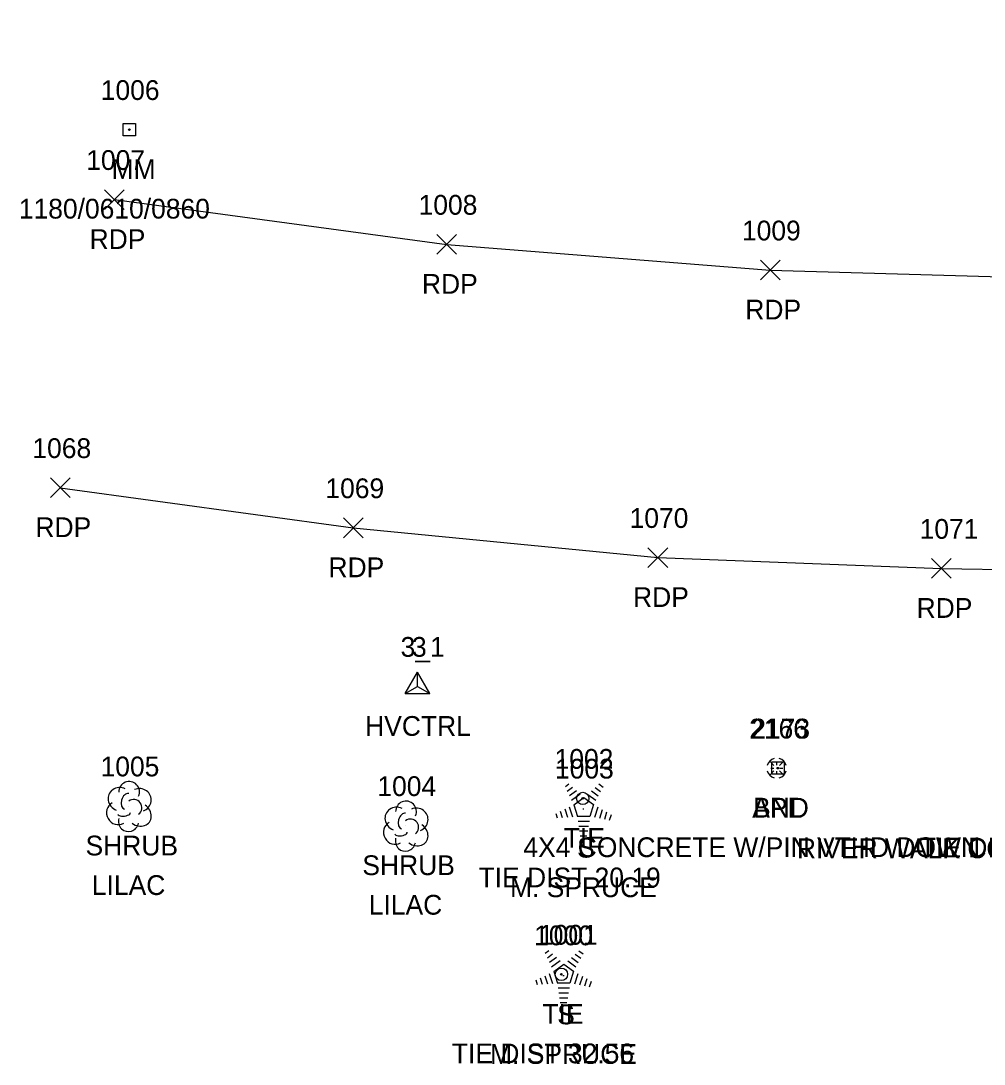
# Model space of a CAD drawing. Extents: x 1600395 to 1603269, y 874955 to 877143.
# Drawn here: x 1601404.6 to 1601502, y 875144.4 to 875250 of the extents above; entities that cross this region are included whole.
import ezdxf

# ---------------------------------------------------------------- set-up
doc = ezdxf.new("R2010")
doc.units = 0
for name, color, linetype in [('C_A', 7, 'Continuous'), ('C_C', 7, 'Continuous'), ('C_I', 7, 'Continuous'), ('CBP', 7, 'Continuous'), ('CPSM', 7, 'Continuous'), ('L_A', 7, 'Continuous'), ('L_C', 7, 'Continuous'), ('L_I', 7, 'Continuous'), ('LSH', 7, 'Continuous'), ('LTC', 7, 'Continuous'), ('M_A', 7, 'Continuous'), ('M_C', 7, 'Continuous'), ('M_I', 7, 'Continuous'), ('MHBP', 7, 'Continuous'), ('MMP', 7, 'Continuous'), ('P_A', 7, 'Continuous'), ('P_I', 7, 'Continuous'), ('P_TIC', 7, 'Continuous'), ('PET', 7, 'Continuous'), ('S_A', 7, 'Continuous'), ('S_C', 7, 'Continuous'), ('S_I', 7, 'Continuous'), ('SRM', 7, 'Continuous')]:
    doc.layers.add(name, color=color, linetype=linetype)

msp = doc.modelspace()

# ---------------------------------------------------------------- linework, layer by layer
at = {"layer": 'CBP'}
for centre, radius in [((1601461.42, 875171.28), 0.625), ((1601461.42, 875171.28), 0.0833), ((1601459.26, 875153.48), 0.625), ((1601459.26, 875153.48), 0.0833)]:
    msp.add_circle(centre, radius, dxfattribs=at)
at = {"layer": 'CPSM'}
for p, q in [((1601443.46, 875181.89), (1601444.71, 875184.06)), ((1601443.46, 875181.89), (1601444.71, 875184.06)), ((1601445.96, 875181.89), (1601444.71, 875184.06)), ((1601444.71, 875182.61), (1601444.71, 875184.06)), ((1601445.96, 875181.89), (1601444.71, 875184.06)), ((1601444.71, 875182.61), (1601444.71, 875184.06)), ((1601443.46, 875181.89), (1601444.71, 875182.61)), ((1601443.46, 875181.89), (1601444.71, 875182.61)), ((1601444.71, 875182.61), (1601444.71, 875182.61)), ((1601444.71, 875182.61), (1601445.96, 875181.89)), ((1601444.71, 875182.61), (1601444.71, 875182.61)), ((1601444.71, 875182.61), (1601445.96, 875181.89)), ((1601443.46, 875181.89), (1601445.96, 875181.89)), ((1601443.46, 875181.89), (1601445.96, 875181.89))]:
    msp.add_line(p, q, dxfattribs=at)
at = {"layer": 'LSH'}
for p, q in [((1601415.48, 875170.51), (1601415.48, 875170.51)), ((1601415.48, 875170.51), (1601415.48, 875170.51)), ((1601443.49, 875168.52), (1601443.49, 875168.52)), ((1601443.49, 875168.52), (1601443.49, 875168.52))]:
    msp.add_line(p, q, dxfattribs=at)
for centre in [(1601415.52, 875171.94), (1601443.54, 875169.96)]:
    msp.add_arc(centre, 1.05, 335.5272, 180.9563, dxfattribs=at)
for centre, major_axis, ratio, start_param, end_param in [((1601414.68, 875171.18), (1.21, -0.51), 0.895232, 1.570796, 4.712389), ((1601415.27, 875170.97), (-0.208, -0.792), 0.645439, 3.141593, 6.283185), ((1601416.52, 875171.09), (-1.14, -0.48), 0.949671, 1.570796, 4.712389), ((1601414.39, 875169.8), (0.58, -1.04), 0.959034, 3.141593, 6.283185), ((1601415.98, 875170.34), (-0.5, 0.667), 0.989748, 3.141593, 6.283185), ((1601415.02, 875169.76), (-0.625, -0.083), 0.423636, 0, 3.141593), ((1601416.48, 875169.68), (-1.09, 0.79), 0.841452, 1.570796, 4.712389), ((1601442.7, 875169.19), (1.21, -0.51), 0.895232, 1.570796, 4.712389), ((1601443.29, 875168.98), (-0.208, -0.792), 0.645439, 3.141593, 6.283185), ((1601444.54, 875169.11), (-1.14, -0.48), 0.949671, 1.570796, 4.712389), ((1601415.48, 875169.01), (0.26, 1.06), 0.942809, 1.570796, 4.712389), ((1601442.41, 875167.81), (0.58, -1.04), 0.959034, 3.141593, 6.283185), ((1601443.99, 875168.36), (-0.5, 0.667), 0.989748, 3.141593, 6.283185), ((1601444.49, 875167.69), (-1.09, 0.79), 0.841452, 1.570796, 4.712389), ((1601443.04, 875167.77), (-0.625, -0.083), 0.423636, 0, 3.141593), ((1601443.49, 875167.02), (0.26, 1.06), 0.942809, 1.570796, 4.712389)]:
    msp.add_ellipse(centre, major_axis=major_axis, ratio=ratio, start_param=start_param, end_param=end_param, dxfattribs=at)
at = {"layer": 'LTC'}
for p, q in [((1601459.66, 875172.5), (1601460.01, 875172.75)), ((1601459.86, 875172.03), (1601460.39, 875172.41)), ((1601460.07, 875171.56), (1601460.78, 875172.08)), ((1601462.31, 875172.04), (1601462.99, 875171.55)), ((1601462.68, 875172.39), (1601463.23, 875171.99)), ((1601463.05, 875172.74), (1601463.47, 875172.43)), ((1601460.28, 875171.1), (1601461.16, 875171.74)), ((1601460.51, 875170.64), (1601461.52, 875171.38)), ((1601461.52, 875171.38), (1601462.52, 875170.65)), ((1601461.94, 875171.69), (1601462.75, 875171.1)), ((1601458.69, 875169.77), (1601458.84, 875169.31)), ((1601459.14, 875169.99), (1601459.35, 875169.34)), ((1601459.6, 875170.21), (1601459.87, 875169.37)), ((1601460.05, 875170.42), (1601460.38, 875169.41)), ((1601460.51, 875170.64), (1601460.9, 875169.45)), ((1601462.52, 875170.65), (1601462.13, 875169.45)), ((1601462.95, 875170.38), (1601462.62, 875169.34)), ((1601463.4, 875170.13), (1601463.11, 875169.25)), ((1601463.84, 875169.88), (1601463.61, 875169.15)), ((1601462.13, 875169.45), (1601460.9, 875169.45)), ((1601462.09, 875168.95), (1601460.94, 875168.95)), ((1601464.29, 875169.63), (1601464.1, 875169.06)), ((1601462, 875168.45), (1601461.02, 875168.45)), ((1601461.92, 875167.95), (1601461.09, 875167.95)), ((1601461.84, 875167.45), (1601461.16, 875167.45)), ((1601457.63, 875155.63), (1601457.99, 875155.89)), ((1601457.84, 875155.16), (1601458.37, 875155.55)), ((1601458.05, 875154.7), (1601458.76, 875155.21)), ((1601460.29, 875155.17), (1601460.97, 875154.68)), ((1601460.66, 875155.52), (1601461.21, 875155.12)), ((1601461.03, 875155.87), (1601461.45, 875155.57)), ((1601458.26, 875154.23), (1601459.14, 875154.87)), ((1601458.49, 875153.78), (1601459.5, 875154.51)), ((1601459.5, 875154.51), (1601460.5, 875153.79)), ((1601459.92, 875154.83), (1601460.73, 875154.24)), ((1601456.67, 875152.91), (1601456.82, 875152.44)), ((1601457.12, 875153.13), (1601457.33, 875152.47)), ((1601457.58, 875153.34), (1601457.85, 875152.51)), ((1601458.03, 875153.56), (1601458.36, 875152.54)), ((1601458.49, 875153.78), (1601458.87, 875152.58)), ((1601460.5, 875153.79), (1601460.11, 875152.58)), ((1601460.93, 875153.52), (1601460.6, 875152.48)), ((1601461.38, 875153.27), (1601461.09, 875152.38)), ((1601461.82, 875153.02), (1601461.59, 875152.29)), ((1601462.27, 875152.77), (1601462.08, 875152.19)), ((1601460.11, 875152.58), (1601458.87, 875152.58)), ((1601460.07, 875152.08), (1601458.92, 875152.08)), ((1601459.98, 875151.58), (1601458.99, 875151.58)), ((1601459.9, 875151.08), (1601459.07, 875151.08)), ((1601459.82, 875150.58), (1601459.14, 875150.58))]:
    msp.add_line(p, q, dxfattribs=at)
at = {"layer": 'MHBP'}
msp.add_lwpolyline([(1601480.54, 875174.97), (1601481.79, 875174.97), (1601481.79, 875173.72), (1601480.54, 875173.72)], close=True, dxfattribs=at)
msp.add_circle((1601481.16, 875174.34), 0.0833, dxfattribs=at)
at = {"layer": 'MMP'}
for p, q in [((1601480.42, 875174.98), (1601480.77, 875174.62)), ((1601481.05, 875174.64), (1601481.05, 875174.94)), ((1601481.34, 875174.62), (1601481.69, 875174.98)), ((1601480.42, 875173.7), (1601480.77, 875174.06)), ((1601480.45, 875174.34), (1601480.75, 875174.34)), ((1601481.05, 875173.74), (1601481.05, 875174.04)), ((1601481.34, 875174.06), (1601481.69, 875173.7)), ((1601481.35, 875174.34), (1601481.65, 875174.34))]:
    msp.add_line(p, q, dxfattribs=at)
for start, end in [(105, 165), (15, 75), (195, 255), (285, 345)]:
    msp.add_arc((1601481.05, 875174.34), 1, start, end, dxfattribs=at)
at = {"layer": 'P_TIC'}
for points in [[(1601413.03, 875230.87), (1601415.03, 875232.87)], [(1601415.03, 875230.87), (1601413.03, 875232.87)], [(1601446.66, 875226.34), (1601448.66, 875228.34)], [(1601448.66, 875226.34), (1601446.66, 875228.34)], [(1601479.39, 875223.74), (1601481.39, 875225.74)], [(1601481.39, 875223.74), (1601479.39, 875225.74)], [(1601407.55, 875201.72), (1601409.55, 875203.72)], [(1601409.55, 875201.72), (1601407.55, 875203.72)], [(1601437.2, 875197.66), (1601439.2, 875199.66)], [(1601439.2, 875197.66), (1601437.2, 875199.66)], [(1601468.02, 875194.65), (1601470.02, 875196.65)], [(1601470.02, 875194.65), (1601468.02, 875196.65)], [(1601496.71, 875193.55), (1601498.71, 875195.55)], [(1601498.71, 875193.55), (1601496.71, 875195.55)]]:
    msp.add_lwpolyline(points, dxfattribs=at)
at = {"layer": 'PET'}
for points in [[(1601414.03, 875231.87), (1601447.66, 875227.34), (1601480.39, 875224.74), (1601507.33, 875223.94), (1601546.89, 875225.24), (1601579.48, 875227.32), (1601621.88, 875231.18), (1601659.14, 875235.73), (1601695.51, 875240.66), (1601718.89, 875244.21), (1601760.24, 875249.95), (1601754.15, 875234.47), (1601747.53, 875218.62)], [(1601408.55, 875202.72), (1601438.2, 875198.66), (1601469.02, 875195.65), (1601497.71, 875194.55), (1601505.99, 875194.41), (1601542.59, 875195.34), (1601577.58, 875198.03), (1601619.13, 875202.15), (1601655.31, 875206.25), (1601695.28, 875211.43), (1601717.66, 875214.5), (1601739.73, 875217.72), (1601747.53, 875218.62)]]:
    msp.add_lwpolyline(points, dxfattribs=at)
at = {"layer": 'SRM'}
msp.add_lwpolyline([(1601414.93, 875239.57), (1601416.18, 875239.57), (1601416.18, 875238.32), (1601414.93, 875238.32)], close=True, dxfattribs=at)
msp.add_circle((1601415.55, 875238.95), 0.0833, dxfattribs=at)

# ---------------------------------------------------------------- texts
at = {"layer": 'C_A'}
for s, p in [('HVCTRL', (1601439.4, 875177.61)), ('HVCTRL', (1601439.4, 875177.61)), ('TIE', (1601459.5, 875166.28)), ('TIE', (1601457.34, 875148.48))]:
    msp.add_text(s, height=2, dxfattribs=at).set_placement(p)
at = {"layer": 'C_C'}
for s, p in [('TIE DIST 62.43', (1601495.53, 875165.31)), ('TIE DIST 20.19', (1601450.88, 875162.28)), ('TIE DIST 32.56', (1601448.18, 875144.48))]:
    msp.add_text(s, height=2, dxfattribs=at).set_placement(p)
at = {"layer": 'C_I'}
for s, p in [('3_1', (1601442.99, 875185.61)), ('3', (1601444.14, 875185.61)), ('1002', (1601458.57, 875174.28)), ('1001', (1601456.98, 875156.48))]:
    msp.add_text(s, height=2, dxfattribs=at).set_placement(p)
at = {"layer": 'L_A'}
for s, p in [('SHRUB', (1601411.11, 875165.51)), ('S', (1601460.85, 875165.29)), ('SHRUB', (1601439.12, 875163.52)), ('S', (1601458.83, 875148.42))]:
    msp.add_text(s, height=2, dxfattribs=at).set_placement(p)
at = {"layer": 'L_C'}
for s, p in [('LILAC', (1601411.75, 875161.51)), ('M. SPRUCE', (1601454.06, 875161.29)), ('LILAC', (1601439.77, 875159.52)), ('M. SPRUCE', (1601452.04, 875144.42))]:
    msp.add_text(s, height=2, dxfattribs=at).set_placement(p)
at = {"layer": 'L_I'}
for s, p in [('1005', (1601412.63, 875173.51)), ('1003', (1601458.61, 875173.29)), ('1004', (1601440.64, 875171.52)), ('1000', (1601456.5, 875156.42))]:
    msp.add_text(s, height=2, dxfattribs=at).set_placement(p)
at = {"layer": 'LTC'}
for p in [(1601461.4, 875170.39), (1601459.38, 875153.53)]:
    msp.add_text('.', height=1.04, rotation=270, dxfattribs=at).set_placement(p)
at = {"layer": 'M_A'}
for s, p in [('APL', (1601478.57, 875169.34)), ('BND', (1601478.65, 875169.34))]:
    msp.add_text(s, height=2, dxfattribs=at).set_placement(p)
at = {"layer": 'M_C'}
msp.add_text('4X4 CONCRETE W/PIN VTHD DOWN', height=2, dxfattribs=at).set_placement((1601455.41, 875165.34))
at = {"layer": 'M_I'}
for s, p in [('2166', (1601478.26, 875177.34)), ('2173', (1601478.47, 875177.34))]:
    msp.add_text(s, height=2, dxfattribs=at).set_placement(p)
at = {"layer": 'P_A'}
for p in [(1601411.52, 875226.87), (1601445.15, 875222.34), (1601477.87, 875219.74), (1601406.04, 875197.72), (1601435.69, 875193.66), (1601466.51, 875190.65), (1601495.2, 875189.55)]:
    msp.add_text('RDP', height=2, dxfattribs=at).set_placement(p)
at = {"layer": 'P_I'}
for s, p in [('1007', (1601411.18, 875234.87)), ('1008', (1601444.81, 875230.34)), ('1009', (1601477.53, 875227.74)), ('1068', (1601405.73, 875205.72)), ('1069', (1601435.38, 875201.66)), ('1070', (1601466.16, 875198.65)), ('1071', (1601495.51, 875197.55))]:
    msp.add_text(s, height=2, dxfattribs=at).set_placement(p)
at = {"layer": 'S_A'}
msp.add_text('MM', height=2, dxfattribs=at).set_placement((1601413.74, 875233.95))
at = {"layer": 'S_C'}
for s, p in [('1180/0610/0860', (1601404.36, 875229.95)), ('RIVER WALK COMMUNITY GARDEN', (1601483.09, 875165.23))]:
    msp.add_text(s, height=2, dxfattribs=at).set_placement(p)
at = {"layer": 'S_I'}
msp.add_text('1006', height=2, dxfattribs=at).set_placement((1601412.65, 875241.95))

doc.saveas('drawing.dxf')
